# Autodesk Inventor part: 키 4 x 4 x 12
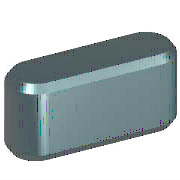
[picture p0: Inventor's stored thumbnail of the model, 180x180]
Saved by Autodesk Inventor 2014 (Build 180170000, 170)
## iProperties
IsCustomPart: 1
Created: 2012-02
Part Number: 키 4 x 4 x 12
Material: 강철, 연강
Description: 키 및 해당 키홈
Document SubType Name: Modeling
Standard: KS B 1311
Designer: mduedu
Standards Organization: KS
Language: ko-KR
Size Designation: 4 x 4 x 12
Categories: <MemberInstance><Categories><Category DisplayName="샤프트 부품" InternalName="7f7aeb1f-a693-4053-b835-cee3144e0d98" Mnemonic="SHFT"><Category DisplayName="키" Interna
Density: 1 g/cm^3
Appearance: 강철
Author: mduedu
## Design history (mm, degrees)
workplane "Work Plane1"
workplane "Work Plane2"
sketch "스케치1"
  geometry: L1 (2, 2)-(10, 2); L2 (10, -2)-(2, -2); L3 (0, 9.4)-(0, -7.4) reference; L4 (-5, 0)-(30, 0) reference; L5 (12, 0)-(12, 7); A1 r 2 centre (2, 0) between (2, 2) and (2, -2); A2 r 2 centre (10, 0) between (10, -2) and (10, 2)
  constraints: 6 end point, 5 point on circle, 4 tangent, 3 point on line, 2 centre point, 1 horizontal, 1 parallel, 1 perpendicular
  dimensions: "d0" = 2 radius of A1 (= 0.5 x PB); "d13" = 2 radius of A2 (= 0.5 x PB); "d14" = 12 distance between parallel lines of L5 L3 (= NLG)
extrude "본체1" new body sketch "스케치1" taper "d3" = 0 deg; stored distance "d4" = 10
workplane "Work Plane3"
body "Solid1"
chamfer "모따기1" distance "d8" = 0.25 (= PHH); stored, may be unused: second distance "d9" = 0.25 (= PHH), angle "d15" = 45 deg
other parameters: "d1" = -2.5 (= -PNT), "d2" = 1.5 (= PH - PNT), "NLG" = 12 [user parameter; used in 3 equation terms], "PB" = 4 [user parameter; used in 2 equation terms], "PNT" = 2.5 [user parameter; used in 2 equation terms], "PH" = 4 [user parameter; used in 1 equation term], "PHH" = 0.25 [user parameter; used in 2 equation terms], "d10" = 0, "d16" = 0, "d17" = 0, "d18" = 0, "PLB2" = 12 (= NLG) [user parameter], "WDMAX" = 12 [user parameter], "PLB1" = 12 (= NLG) [user parameter], "RR" = 0.08 [user parameter], "PUEB" = 1.8 [user parameter]
